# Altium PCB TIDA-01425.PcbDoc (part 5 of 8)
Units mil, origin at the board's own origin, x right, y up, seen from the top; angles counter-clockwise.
Board outline 7000 x 3600 mil, 6 copper layers (Layer 1 - Top Layer, Layer 2 - GND, Layer 3 - Signal / PWR, Layer 4 - Signal / PWR, Layer 5 - PWR, Layer 6 - Bottom Layer), stack 60.4 mil thick; 495 components, 307 nets, 2058 pads, 1870 vias.
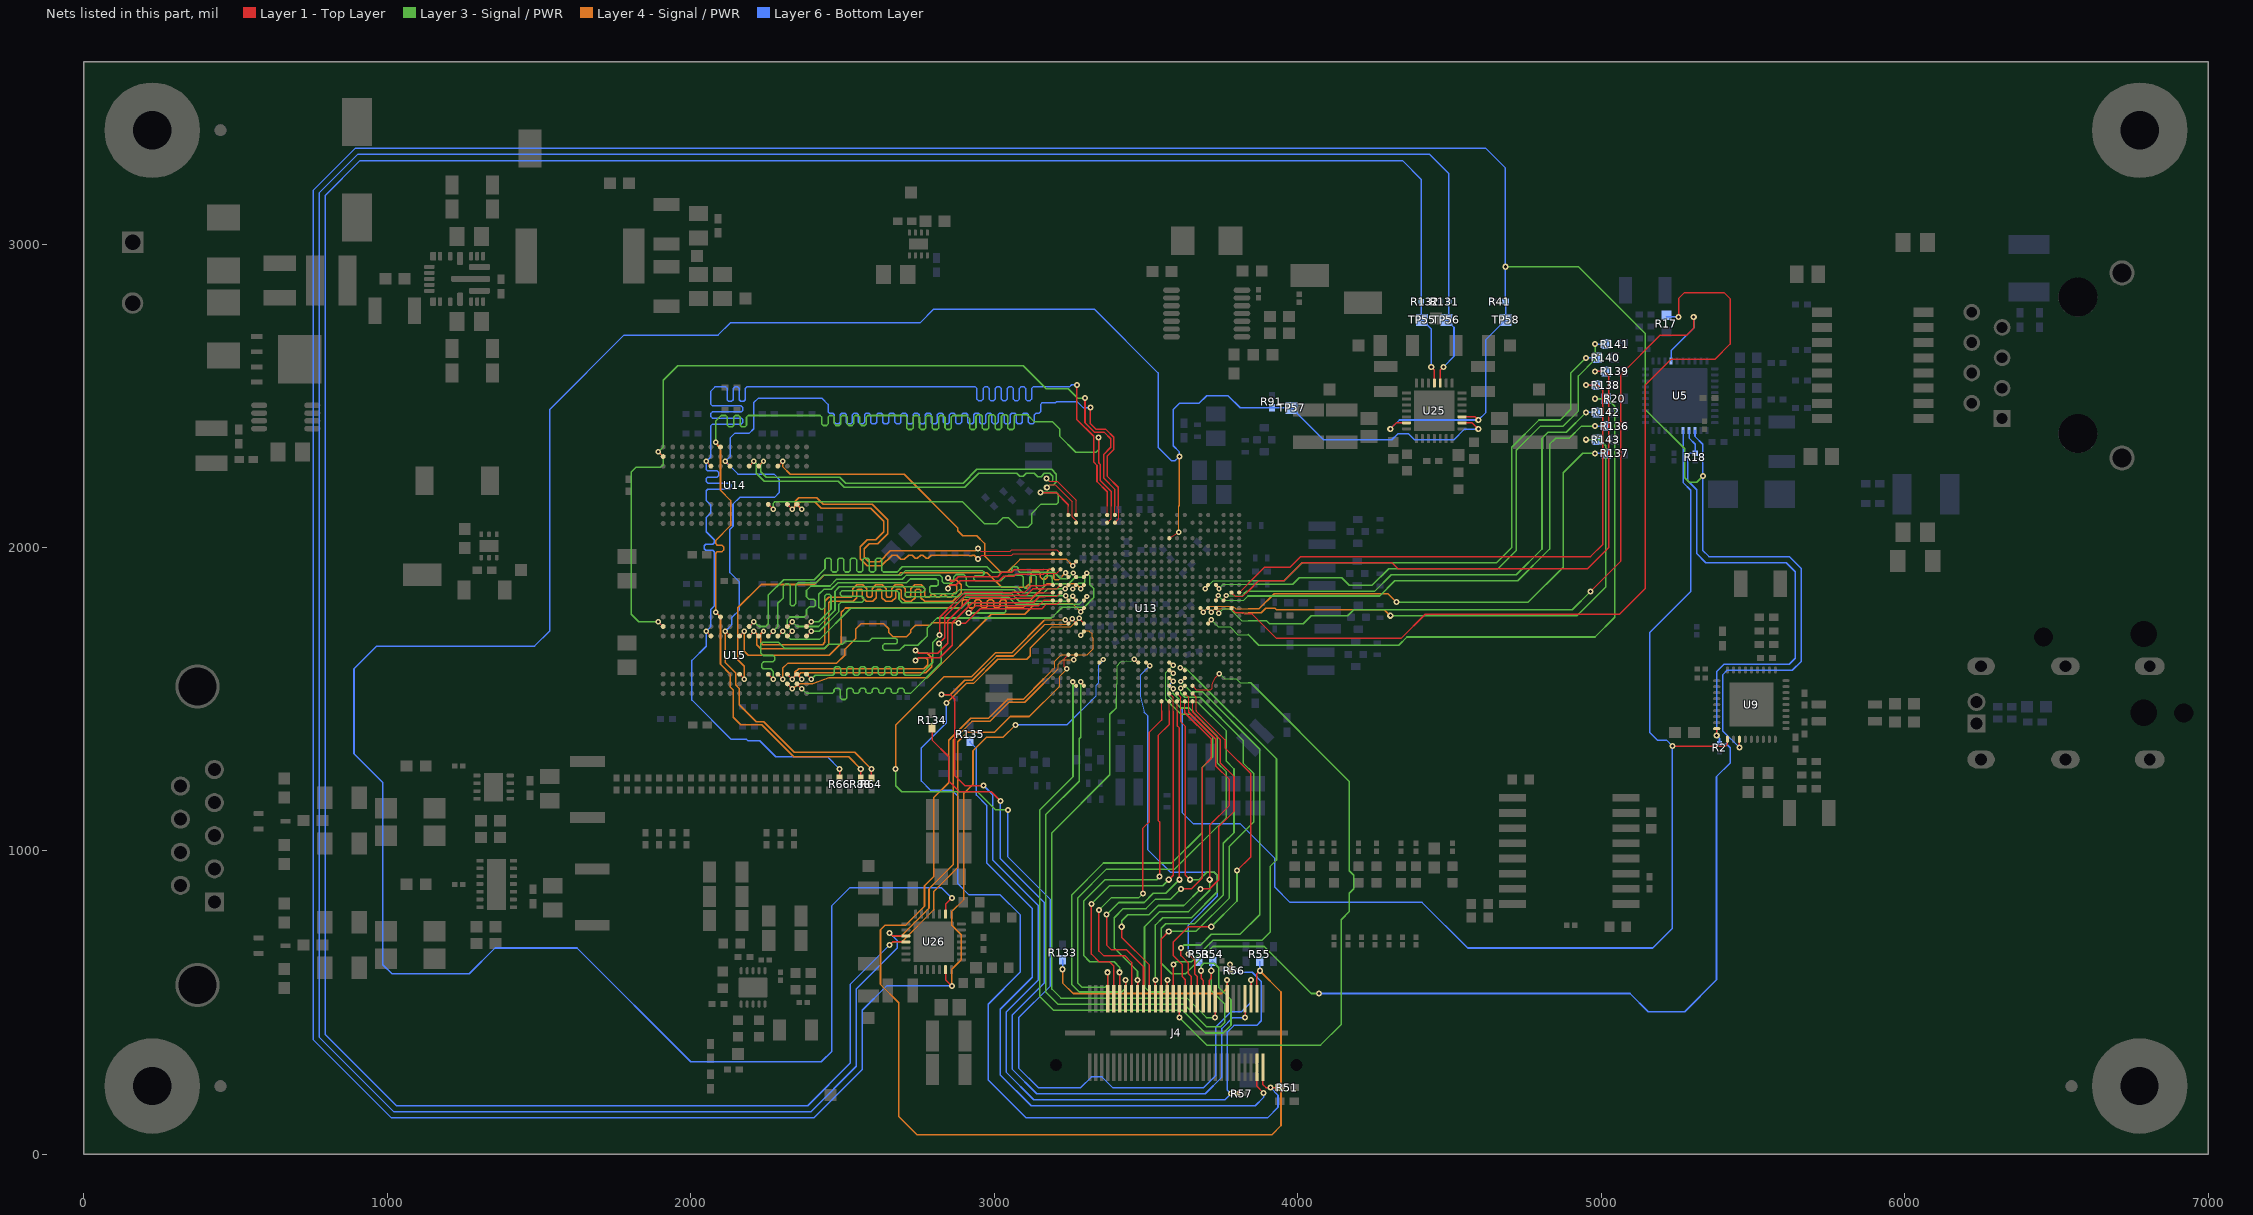
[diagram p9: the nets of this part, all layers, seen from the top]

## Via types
v1: diameter 20, hole 10, Layer 1 - Top Layer to Layer 6 - Bottom Layer, tented both sides, 1119 vias
v2: diameter 20, hole 9.99, Layer 1 - Top Layer to Layer 6 - Bottom Layer, tented both sides, 298 vias
v3: diameter 18, hole 7.99, Layer 1 - Top Layer to Layer 6 - Bottom Layer, tented both sides, 203 vias
v4: diameter 18, hole 8, Layer 1 - Top Layer to Layer 6 - Bottom Layer, tented both sides, 177 vias
v5: diameter 19.68, hole 7.87, Layer 1 - Top Layer to Layer 6 - Bottom Layer, tented both sides, 41 vias
v6: diameter 20, hole 10, Layer 1 - Top Layer to Layer 6 - Bottom Layer, 27 vias
v7: diameter 19.68, hole 7.87, Layer 1 - Top Layer to Layer 6 - Bottom Layer, 5 vias

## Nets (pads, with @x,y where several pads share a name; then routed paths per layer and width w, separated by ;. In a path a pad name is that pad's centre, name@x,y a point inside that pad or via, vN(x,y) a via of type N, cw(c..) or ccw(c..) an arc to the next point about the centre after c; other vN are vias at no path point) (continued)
H_DDR1_D20: U13.T22 U15.E3 | length 1681.3
  Layer 1 - Top Layer w4: U15.E3@2255.24,1707.99 v4(2270.98,1723.73)
  Layer 1 - Top Layer w4.05: v3(3259.1,1863.1) U13.T22@3269.68,1876.77
  Layer 3 - Signal / PWR w5.25: v4(2270.98,1723.73) 2286.84,1739.59 2286.84,1815.84 2304,1833 2304,1871 2313.82,1880.82 2321.18,1880.82 2327,1875 2327,1813.08 2332,1808.08 2339.08,1808.08 2345.2,1814.2 2345.2,1875.2 2353.6,1883.6 2412.5,1883.6 2437.2,1908.3 2692.3,1908.3 2707.8,1923.8 2961.2,1923.8 2966,1919 2966,1911.62 2960.8,1906.42 2936.85,1906.42 2933,1902.57 2933,1895.21 2938.21,1890 3022.51,1890 3036.98,1904.47 3041.55,1904.47 3041.91,1904.83 3043.43,1904.83 3046.4,1907.8 3090.4,1907.8 3095.6,1902.6 3095.6,1871.2 3100.8,1866 3111.2,1866 3116.4,1871.2 3116.4,1902.6 3121.6,1907.8 3134,1907.8 3137.9,1903.9 3137.9,1870.1 3144.82,1863.18 3155.18,1863.18 3163,1871 3163,1899 3171,1907 3185.8,1907 3191,1901.8 3191,1885.2 3196.2,1880 3245,1880 3266.99,1901.99 3293.52,1901.99 3298.72,1896.79 3298.72,1886.72 3294,1882 3278,1882 v3(3259.1,1863.1)
H_DDR1_D21: U13.U22 U15.G2 | length 1680
  Layer 1 - Top Layer w4: U15.G2@2192.24,1739.49 v4(2207.98,1755.22) ; v3(3259.7,1915.8) U13.U22@3269.68,1902.36
  Layer 3 - Signal / PWR w5.25: v4(2207.98,1755.22) 2223.7,1739.5 2246.59,1739.5 2255.3,1748.21 2255.3,1843.37 2305.93,1894 2406.5,1894 2442.2,1929.7 2442.2,1959.8 2447.4,1965 2457.8,1965 2463,1959.8 2463,1924.2 2468.2,1919 2478.6,1919 2483.8,1924.2 2483.8,1959.8 2489,1965 2499.4,1965 2504.6,1959.8 2504.6,1924.2 2509.8,1919 2520.2,1919 2525.4,1924.2 2525.4,1959.8 2530.6,1965 2541,1965 2546.2,1959.8 2546.2,1924.2 2551.4,1919 2561.8,1919 2567,1924.2 2567,1959.8 2572.2,1965 2582.6,1965 2587.8,1959.8 2587.8,1924.2 2593,1919 2603.4,1919 2608.6,1924.2 2608.6,1959.8 2613.8,1965 2624.2,1965 2629.4,1959.8 2629.4,1924.2 2634.6,1919 2680,1919 2697.1,1936.1 2975.9,1936.1 2993.95,1918.05 3052.95,1918.05 3058.15,1923.25 3058.15,1931.8 3063.35,1937 3073.75,1937 3078.95,1931.8 3078.95,1923.25 3084.15,1918.05 3197.95,1918.05 3219,1897 3240.9,1897 v3(3259.7,1915.8)
H_DDR1_D22: U13.U23 U15.H7 | length 1552
  Layer 1 - Top Layer w4: U15.H7@2160.75,1582 v4(2176.49,1566.26) ; v3(3234.8,1916.5) U13.U23@3244.09,1902.36
  Layer 4 - Signal / PWR w5.25: v4(2176.49,1566.26) 2176.49,1608.5 2155,1629.99 2155,1801 2231.9,1877.9 2407.7,1877.9 2438.6,1908.8 2683.8,1908.8 2691,1916 2977,1916 3024.6,1868.4 3103.4,1868.4 3121,1886 3121,1916 3127,1922 3145.8,1922 3151,1916.8 3151,1903 3158.03,1895.97 3169.39,1895.97 3174.59,1901.17 3174.59,1921.8 3180.79,1928 3189.19,1928 3195.39,1921.8 3195.39,1898.2 3200.59,1893 3211.3,1893 v3(3234.8,1916.5)
H_DDR1_D23: U13.T21 U15.H3 | length 1552.8
  Layer 1 - Top Layer w4: U15.H3@2160.75,1707.99 v4(2176.49,1723.73) ; v3(3285.5,1864.1) U13.T21@3295.28,1876.77
  Layer 4 - Signal / PWR w5.25: v4(2176.49,1723.73) 2176.49,1657.51 2189,1645 2456,1645 2495.5,1684.5 2495.5,1786.5 2509.6,1800.6 2888.74,1800.6 2893.94,1805.8 2893.94,1822.8 2899.14,1828 2909.54,1828 2914.74,1822.8 2914.74,1805.8 2919.94,1800.6 2930.34,1800.6 2935.54,1805.8 2935.54,1822.8 2940.74,1828 2951.14,1828 2956.34,1822.8 2956.34,1805.8 2961.54,1800.6 2971.94,1800.6 2977.14,1805.8 2977.14,1822.8 2982.34,1828 2992.74,1828 2997.94,1822.8 2997.94,1805.8 3003.14,1800.6 3013.54,1800.6 3018.74,1805.8 3018.74,1822.8 3023.94,1828 3034.34,1828 3039.54,1822.8 3039.54,1805.8 3044.74,1800.6 3094.6,1800.6 3174,1880 3269.6,1880 v3(3285.5,1864.1)
H_DDR1_D24: U13.T23 U15.C3 | length 1232.6
  Layer 1 - Top Layer w4: U15.C3@2318.23,1707.99 v4(2333.97,1723.73) ; v3(3234.3,1863.7) U13.T23@3244.09,1876.77
  Layer 3 - Signal / PWR w5.25: v4(2333.97,1723.73) 2318.3,1739.4 2318.3,1762.4 2326.8,1770.9 2374.51,1770.9 2381.2,1777.59 2381.2,1795.2 2390,1804 2405,1804 2410,1809 2410,1824.45 2404.75,1829.7 2389.3,1829.7 2381.06,1837.94 2381.06,1858.06 2396.1,1873.1 2458.5,1873.1 2480.4,1895 2697,1895 2711,1909 2820,1909 2829,1900 2829,1887.2 2834.2,1882 2859,1882 2867,1890 2867,1903 2875,1911 2899,1911 2908,1902 2908,1877 2914,1871 3074,1871 3094,1851 3163.99,1851 3176.69,1863.7 v3(3234.3,1863.7)
H_DDR1_D25: U13.T25 U15.A7 | length 1283.8
  Layer 1 - Top Layer w4: U15.A7@2381.22,1582.01 v4(2396.96,1566.26)
  Layer 1 - Top Layer w5: v1(2820,1711) 2820,1770 2901.7,1851.7 3028.37,1851.7 3028.73,1851.34 3059.01,1851.34 3059.37,1851.7 3099.7,1851.7 3122,1874 3161,1874 3163.77,1876.77 U13.T25@3192.91,1876.77
  Layer 3 - Signal / PWR w5.25: v4(2396.96,1566.26) 2409.7,1579 2467.5,1579 2472.7,1584.2 2472.7,1601.8 2477.9,1607 2488.3,1607 2493.5,1601.8 2493.5,1584.2 2498.7,1579 2509.1,1579 2514.3,1584.2 2514.3,1601.8 2519.5,1607 2529.9,1607 2535.1,1601.8 2535.1,1584.2 2540.3,1579 2550.7,1579 2555.9,1584.2 2555.9,1601.8 2561.1,1607 2571.5,1607 2576.7,1601.8 2576.7,1584.2 2581.9,1579 2592.3,1579 2597.5,1584.2 2597.5,1601.8 2602.7,1607 2613.1,1607 2618.3,1601.8 2618.3,1584.2 2623.5,1579 2633.9,1579 2639.1,1584.2 2639.1,1601.8 2644.3,1607 2654.7,1607 2659.9,1601.8 2659.9,1584.2 2665.1,1579 2675.5,1579 2680.7,1584.2 2680.7,1601.8 2685.9,1607 2696.3,1607 2701.5,1601.8 2701.5,1584.2 2706.7,1579 2755,1579 2797.6,1621.6 2797.6,1687.08 2801.37,1690.85 ; 2801.37,1690.89 2820,1709.52 v1(2820,1711)
H_DDR1_D26: U13.T24 U15.B8 | length 1290.2
  Layer 1 - Top Layer w4: U15.B8@2349.72,1550.51 v4(2365.46,1534.77) ; 3163,1864 3205.73,1864 U13.T24@3218.5,1876.77
  Layer 1 - Top Layer w5: v1(2818,1684) 2836.5,1702.5 2836.5,1772.34 2905.86,1841.7 3024.22,1841.7 3024.58,1841.34 3063.16,1841.34 3063.52,1841.7 3105.69,1841.7 3127.99,1864 3163,1864
  Layer 3 - Signal / PWR w5.25: v4(2365.46,1534.77) 2381.34,1518.89 2466.47,1518.89 2471.72,1524.14 2471.72,1530.75 2476.97,1536 2487.47,1536 2492.72,1530.75 2492.72,1504.14 2497.97,1498.89 2508.47,1498.89 2513.72,1504.14 2513.72,1530.75 2518.97,1536 2529.47,1536 2534.72,1530.75 2534.72,1524.14 2539.97,1518.89 2550.47,1518.89 2555.72,1524.14 2555.72,1530.75 2560.97,1536 2571.47,1536 2576.72,1530.75 2576.72,1524.14 2581.97,1518.89 2592.47,1518.89 2597.72,1524.14 2597.72,1530.75 2602.97,1536 2613.47,1536 2618.72,1530.75 2618.72,1524.14 2623.97,1518.89 2634.47,1518.89 2639.72,1524.14 2639.72,1530.75 2644.97,1536 2655.47,1536 2660.72,1530.75 2660.72,1524.14 2665.97,1518.89 2676.47,1518.89 2681.72,1524.14 2681.72,1530.75 2686.97,1536 2697.47,1536 2702.72,1530.75 2702.72,1524.14 2707.97,1518.89 2723.89,1518.89 2825,1620 2825,1677 v1(2818,1684)
H_DDR1_D27: U13.P21 U15.A3 | length 1235.1
  Layer 1 - Top Layer w4: U15.A3@2381.22,1707.99 v4(2396.96,1723.73)
  Layer 1 - Top Layer w4.05: U13.P21@3295.28,1825.59 v3(3305.5,1838.3)
  Layer 3 - Signal / PWR w5.25: v4(2396.96,1723.73) 2423.16,1723.73 2488,1788.57 2488,1812 2496,1820 2564.8,1820 2570,1825.2 2570,1832.56 2563.32,1839.24 2498.2,1839.24 2493,1844.44 2493,1851.8 2498.2,1857 2679,1857 2686,1850 2686,1829 2697,1818 2882,1818 2900,1836 3048,1836 3071.64,1812.36 3279.56,1812.36 v3(3305.5,1838.3)
H_DDR1_D28: U13.N21 U15.C8 | length 1110.4
  Layer 1 - Top Layer w4: U15.C8@2318.23,1550.51 v4(2333.97,1534.77) ; v3(3285.6,1787.5) U13.N21@3295.28,1800
  Layer 4 - Signal / PWR w5.25: v4(2333.97,1534.77) 2360.46,1550.5 2401.43,1550.5 2454.6,1570 2780,1570 2990,1780 3100,1780 3135.1,1815.1 3258,1815.1 v3(3285.6,1787.5)
H_DDR1_D29: U13.P22 U15.C2 | length 1235.8
  Layer 1 - Top Layer w4: U15.C2@2318.23,1739.49 v4(2333.97,1755.22)
  Layer 1 - Top Layer w4.05: v3(3258.8,1839.9) U13.P22@3269.68,1825.59
  Layer 3 - Signal / PWR w5.25: v4(2333.97,1755.22) 2349.79,1739.4 2421.1,1739.4 2475,1793.3 2475,1856 2489.5,1870.5 2765.5,1870.5 2771,1865 2771,1859 2765,1853 2711,1853 2706,1848 2706,1842 2711,1837 2881,1837 2892,1848 3057,1848 3082.39,1822.61 3241.51,1822.61 v3(3258.8,1839.9)
H_DDR1_D30: U13.P23 U15.A2 | length 1236.7
  Layer 1 - Top Layer w4: U15.A2@2381.22,1739.49 v4(2396.96,1755.22) ; v3(3235.9,1840.6) U13.P23@3244.09,1825.59
  Layer 3 - Signal / PWR w5.25: v4(2396.96,1755.22) 2421.22,1755.22 2462,1796 2462,1840.8 2456.8,1846 2447.2,1846 2442,1840.8 2442,1803.6 2435.4,1797 2428.04,1797 2422,1803.04 2422,1845.57 2438.56,1862.13 2462.92,1862.13 2483.79,1883 2710,1883 2723,1896 2809,1896 2815,1890 2815,1877 2811,1873 2791,1873 2787,1869 2787,1853 2792.75,1847.25 2871.25,1847.25 2884,1860 3066,1860 3085.4,1840.6 v3(3235.9,1840.6)
H_DDR1_D31: U13.P24 U15.D7 | length 1143.4
  Layer 1 - Top Layer w4: U15.D7@2286.73,1582.01 v4(2302.47,1566.26) ; 3163,1804.41 3171.39,1812.8 3205.71,1812.8 U13.P24@3218.5,1825.59
  Layer 1 - Top Layer w5: v1(2882.66,1750.74) 2905.99,1750.74 2922.75,1767.5 2953.56,1798.3 3006.23,1798.3 3006.59,1797.94 3081.15,1797.94 3081.51,1798.3 3156.89,1798.3 3163,1804.41
  Layer 4 - Signal / PWR w5.25: v4(2302.47,1566.26) 2302.47,1601.47 2320,1619 2481,1619 2507,1645 2507,1664 2544,1701 2544,1732 2560,1748 2636.2,1748 2652,1732.2 2652,1720 2666,1706 2711,1706 2725,1720 2725,1728 2740,1743 2786.2,1743 2794.98,1751.78 2881.62,1751.78 v1(2882.66,1750.74)
H_DDR1_DQM0: U13.AE23 U14.E7 | length 1317.5
  Layer 1 - Top Layer w4: U14.E7@2255.24,2142.01 v4(2270.98,2126.26) ; U13.AE23@3244.09,2107.09 3244.09,2136
  Layer 1 - Top Layer w5: v1(3153,2181) 3204,2181 3244.09,2140.91 3244.09,2136
  Layer 3 - Signal / PWR w5.25: v4(2270.98,2126.26) 2270.98,2144.98 2277,2151 2895,2151 2968,2078 3009,2078 3029,2098 3047,2098 3079,2066 3110,2066 3124,2080 3124,2113 3154,2143 3205.8,2143 3211,2148.2 3211,2175.05 3205.05,2181 v1(3153,2181)
H_DDR1_DQM1: U13.W22 U14.D3 | length 1211.9
  Layer 1 - Top Layer w4: U14.D3@2286.73,2267.99 v4(2302.47,2283.73) ; v3(3258.7,1940) U13.W22@3269.68,1953.54
  Layer 4 - Signal / PWR w5.25: v4(2302.47,2283.73) 2302.47,2266.53 2328,2241 2703,2241 2880,2064 2880,2055 2896.1,2038.9 2942.1,2038.9 2968,2013 2968,1973 3022.5,1918.5 3042.9,1918.5 3084.9,1960.5 3238.2,1960.5 v3(3258.7,1940)
H_DDR1_DQM2: U13.U21 U15.E7 | length 1679.2
  Layer 1 - Top Layer w4: U15.E7@2255.24,1582.01 v4(2270.98,1566.26)
  Layer 1 - Top Layer w4.05: U13.U21@3295.28,1902.36 v3(3304.3,1915.7)
  Layer 3 - Signal / PWR w5.25: v4(2270.98,1566.26) 2270.98,1592 2262.98,1600 2238.47,1600 2233.22,1605.25 2233.22,1616.21 2240.63,1623.62 2270.61,1623.62 2276.28,1629.29 2276.28,1638.72 2271,1644 2238,1644 2231,1651 2231,1683 2235,1687 2290,1687 2309,1668 2441,1668 2454,1681 2500,1681 2510,1691 2587,1691 2597,1701 2674.75,1701 2680,1695.75 2680,1686 2676,1682 2638.25,1682 2633,1676.75 2633,1666.25 2638.25,1661 2688,1661 2704.63,1677.63 2748.13,1677.63 2779.6,1709.1 2779.6,1735.36 2811.61,1767.37 3188.37,1767.37 3224.12,1803.12 3296.12,1803.12 3328,1835 3328,1865.01 3314,1879.01 3314,1906 v3(3304.3,1915.7)
H_DDR1_DQM3: U13.P25 U15.D3 | length 1263.6
  Layer 1 - Top Layer w4: U15.D3@2286.73,1707.99 v4(2302.47,1723.73)
  Layer 1 - Top Layer w5: v1(2915.92,1784) 2940.22,1808.3 3010.38,1808.3 3010.74,1807.94 3077,1807.94 3077.36,1808.3 3146.29,1808.3 3163.58,1825.59 U13.P25@3192.91,1825.59
  Layer 3 - Signal / PWR w5.25: v4(2302.47,1723.73) 2329.2,1697 2424,1697 2527,1800 2892,1800 2910,1818 3032.75,1818 3038,1812.75 3038,1789 3033,1784 v1(2915.92,1784)
H_DDR1_DQS0_N: U13.AE22 U14.G3 | length 1316.8
  Layer 1 - Top Layer w4: v1(3172,2227) 3181,2218 3208,2218 3269.81,2156.19 3269.81,2117.96 3269.86,2117.91 3269.86,2107.26 U13.AE22@3269.68,2107.09
  Layer 1 - Top Layer w4.05: U14.G3@2192.24,2267.99 v4(2207.98,2283.73)
  Layer 3 - Signal / PWR w4: v1(3172,2227) 3181,2218 3189,2218 3193,2222
  Layer 3 - Signal / PWR w4.5: v4(2207.98,2283.73) 2216,2275.71 2216,2243.99 2241.99,2218 2485.2,2218 2505.2,2198 2902.8,2198 2948.8,2244 3074,2244 3084,2234 3095,2234 3105,2244 3132,2244 3143,2233 3154,2233 3165,2244 3183.2,2244 3193,2234.2 3193,2222
H_DDR1_DQS0_P: U13.AD22 U14.F3 | length 1328
  Layer 1 - Top Layer w4: v1(3173,2198) 3182,2207 3200.61,2207 3256.81,2150.8 3256.81,2117.92
  Layer 1 - Top Layer w4.05: U14.F3@2223.74,2267.99 v4(2239.48,2283.73) ; 3256.81,2117.92 3256.81,2101.53 3269.69,2088.65 U13.AD22@3269.68,2081.5
  Layer 3 - Signal / PWR w4: v1(3173,2198) 3173,2199 3181,2207 3196,2207
  Layer 3 - Signal / PWR w4.5: v4(2239.48,2283.73) 2230,2274.25 2230,2249.79 2247.79,2232 2491,2232 2511,2212 2897,2212 2943,2258 3189,2258 3205,2242 3205,2216 3196,2207
H_DDR1_DQS1_N: U13.Y25 U14.B7 | length 1229.4
  Layer 1 - Top Layer w4: v1(2947,1961.66) 2959.45,1974.11 3005.89,1974.11 3006,1974 3057.39,1974 3062.41,1979.02 3074.96,1979.02 3075.07,1979.13 3182.16,1979.13 3182.26,1979.03 3192.81,1979.03 U13.Y25@3192.91,1979.13
  Layer 1 - Top Layer w4.05: U14.B7@2349.72,2142.01 v4(2365.46,2126.26)
  Layer 4 - Signal / PWR w4.5: v4(2365.46,2126.26) 2356,2135.72 2356,2145 2361,2150 2409.18,2150 2430.58,2128.6 2592.6,2128.6 2635.6,2085.6 2635.6,2051.6 2610,2026 2582,2026 2558,2002 2558,1962.2 2581.2,1939 2627.8,1939 2663.8,1975 2678,1975 2692,1961 2704,1961 2718,1975 2729,1975 2739.81,1964.19 2746.19,1964.19 2757,1975 2765,1975 2775.81,1964.19 2782.19,1964.19 2793,1975 2916,1975 2918.81,1972.19 2925.19,1972.19 2928,1975 2933.66,1975 v1(2947,1961.66)
H_DDR1_DQS1_P: U13.Y24 U14.C7 | length 1247.3
  Layer 1 - Top Layer w4: v1(2947,1996.34) 2956.23,1987.11 2986.7,1987.11 2986.81,1987 3052,1987 3057.02,1992.02 3069.57,1992.02 3069.68,1992.13 3187.55,1992.13 3187.65,1992.03 3205.6,1992.03 U13.Y24@3218.5,1979.13
  Layer 1 - Top Layer w4.05: U14.C7@2318.23,2142.01 v4(2333.97,2126.26)
  Layer 4 - Signal / PWR w4.5: v4(2333.97,2126.26) 2342,2134.29 2342,2150.8 2355.2,2164 2414.98,2164 2436.38,2142.6 2598.4,2142.6 2649.6,2091.4 2649.6,2045.8 2615.8,2012 2587.8,2012 2572,1996.2 2572,1968 2587,1953 2622,1953 2658,1989 2939.66,1989 v1(2947,1996.34)
H_DDR1_DQS2_N: U13.V25 U15.G3 | length 1600
  Layer 1 - Top Layer w4: 3163,1927.5 3163.55,1928.05 3192.81,1928.05 U13.V25@3192.91,1927.95
  Layer 1 - Top Layer w4.05: U15.G3@2192.24,1707.99 v4(2207.98,1723.73)
  Layer 1 - Top Layer w4.4: v1(2847,1899.34) 2857.34,1889 2867,1889 2882,1904 3011,1904 3025.4,1918.4 3058.4,1918.4 3066.5,1926.5 3162,1926.5 3163,1927.5
  Layer 4 - Signal / PWR w4.5: v4(2207.98,1723.73) 2216.73,1714.98 2216.73,1679.91 2230.64,1666 2439.8,1666 2455,1681.2 2455,1817.5 2459.5,1822 2534.7,1822 2547.4,1834.7 2547.4,1858.5 2551.9,1863 2560.9,1863 2565.4,1858.5 2565.4,1834.7 2578.1,1822 2598.7,1822 2611.4,1834.7 2611.4,1858.5 2615.9,1863 2624.9,1863 2629.4,1858.5 2629.4,1834.7 2642.1,1822 2662.7,1822 2675.4,1834.7 2675.4,1858.5 2679.9,1863 2688.9,1863 2693.4,1858.5 2693.4,1834.7 2706.1,1822 2726.7,1822 2739.4,1834.7 2739.4,1858.5 2743.9,1863 2752.9,1863 2757.4,1858.5 2757.4,1834.7 2770.1,1822 2863,1822 2891,1850 2891,1877.3 2876.4,1891.9 2854.44,1891.9 v1(2847,1899.34)
H_DDR1_DQS2_P: U13.V24 U15.F3 | length 1586.2
  Layer 1 - Top Layer w4: 3163,1913.5 3163.85,1914.35 3186.95,1914.35 3187.65,1915.05 3205.6,1915.05 3205.76,1915.21
  Layer 1 - Top Layer w4.05: U15.F3@2223.74,1707.99 v4(2239.48,1723.73) ; 3205.76,1915.21 U13.V24@3218.5,1927.95
  Layer 1 - Top Layer w4.4: v1(2847,1864.66) 2857.34,1875 2872.8,1875 2887.8,1890 3016.8,1890 3031.2,1904.4 3064.2,1904.4 3072.3,1912.5 3162,1912.5 3163,1913.5
  Layer 4 - Signal / PWR w4.5: v4(2239.48,1723.73) 2230.73,1714.98 2230.73,1685.71 2236.44,1680 2434,1680 2441,1687 2441,1823.3 2453.7,1836 2528.9,1836 2533.4,1840.5 2533.4,1864.3 2546.1,1877 2566.7,1877 2579.4,1864.3 2579.4,1840.5 2583.9,1836 2592.9,1836 2597.4,1840.5 2597.4,1864.3 2610.1,1877 2630.7,1877 2643.4,1864.3 2643.4,1840.5 2647.9,1836 2656.9,1836 2661.4,1840.5 2661.4,1864.3 2674.1,1877 2694.7,1877 2707.4,1864.3 2707.4,1840.5 2711.9,1836 2720.9,1836 2725.4,1840.5 2725.4,1864.3 2738.1,1877 2758.7,1877 2771.4,1864.3 2771.4,1840.5 2775.9,1836 2785,1836 2794.31,1845.31 2800.69,1845.31 2810,1836 2819,1836 2829.31,1846.31 2835.69,1846.31 2846,1836 2857.2,1836 2863.6,1842.4 2863.6,1846.9 2868.1,1851.4 2872.6,1851.4 2877,1855.8 2877,1871.5 2870.6,1877.9 2854.9,1877.9 2847,1870 v1(2847,1864.66)
H_DDR1_DQS3_N: U13.R25 U15.B7 | length 1163.9
  Layer 1 - Top Layer w4: 3163,1851 3192.73,1851 U13.R25@3192.91,1851.18
  Layer 1 - Top Layer w4.05: U15.B7@2349.72,1582.01 v4(2365.46,1566.26)
  Layer 1 - Top Layer w4.4: v1(2741,1661) 2750.85,1651.15 2814.15,1651.15 2847,1684 2847,1757.8 2921.2,1832 3020.2,1832 3020.56,1831.64 3067.18,1831.64 3067.54,1832 3123,1832 3142,1851 3163,1851
  Layer 4 - Signal / PWR w4.5: v4(2365.46,1566.26) 2357,1574.72 2357,1582.5 2361.5,1587 2774,1587 2794,1607 2794,1636 2778.85,1651.15 2750.85,1651.15 v1(2741,1661)
H_DDR1_DQS3_P: U13.R24 U15.C7 | length 1172.3
  Layer 1 - Top Layer w4: 3163,1837 3168.52,1837 3170,1838.48 3205.8,1838.48 U13.R24@3218.5,1851.18
  Layer 1 - Top Layer w4.05: U15.C7@2318.23,1582.01 v4(2333.97,1566.26)
  Layer 1 - Top Layer w4.4: v1(2741,1627.31) 2750.84,1637.15 2819.95,1637.15 2861,1678.2 2861,1752 2927,1818 3014.4,1818 3014.76,1817.64 3072.98,1817.64 3073.34,1818 3128.8,1818 3147.8,1837 3163,1837
  Layer 4 - Signal / PWR w4.5: v4(2333.97,1566.26) 2343,1575.29 2343,1588.3 2355.7,1601 2768.2,1601 2780,1612.8 2780,1630.2 2773.05,1637.15 2750.84,1637.15 v1(2741,1627.31)
H_DDR1_ODT0: R88.1 U13.AD18 U14.K1 U15.K1 | length 4323.8
  Layer 1 - Top Layer w4: v4(2082.02,1786.72) U15.K1@2097.76,1770.98 ; v4(2082.02,2346.72) U14.K1@2097.76,2330.98 ; U13.AD18@3372.05,2081.5 3384.74,2094.19 3384.74,2136
  Layer 1 - Top Layer w5: R88.1@2560,1239.68 v1(2560,1270) ; v1(3344,2362) 3344,2279 3348.5,2274.5 3348.5,2221.42 3384.74,2185.18 3384.74,2136
  Layer 3 - Signal / PWR w5.25: v4(2082.02,2346.72) 2082.02,2416.52 2100.4,2434.9 2115.29,2434.9 2120.54,2429.65 2120.54,2402.35 2125.79,2397.1 2136.29,2397.1 2141.54,2402.35 2141.54,2429.65 2146.79,2434.9 2157.29,2434.9 2162.54,2429.65 2162.54,2402.35 2167.79,2397.1 2178.29,2397.1 2183.54,2402.35 2183.54,2429.65 2188.79,2434.9 2425.98,2434.9 2431.23,2429.65 2431.23,2407.05 2436.48,2401.8 2446.98,2401.8 2452.23,2407.05 2452.23,2429.65 2457.48,2434.9 2467.98,2434.9 2473.23,2429.65 2473.23,2407.05 2478.48,2401.8 2488.98,2401.8 2494.23,2407.05 2494.23,2429.65 2499.48,2434.9 2509.98,2434.9 2515.23,2429.65 2515.23,2407.05 2520.48,2401.8 2530.98,2401.8 2536.23,2407.05 2536.23,2429.65 2541.48,2434.9 2551.98,2434.9 2557.23,2429.65 2557.23,2407.05 2562.48,2401.8 2572.98,2401.8 2578.23,2407.05 2578.23,2429.65 2583.48,2434.9 2706.34,2434.9 2711.59,2429.65 2711.59,2393.95 2716.84,2388.7 2727.34,2388.7 2732.59,2393.95 2732.59,2429.65 2737.84,2434.9 2748.34,2434.9 2753.59,2429.65 2753.59,2393.95 2758.84,2388.7 2769.34,2388.7 2774.59,2393.95 2774.59,2429.65 2779.84,2434.9 2790.34,2434.9 2795.59,2429.65 2795.59,2393.95 2800.84,2388.7 2811.34,2388.7 2816.59,2393.95 2816.59,2429.65 2821.84,2434.9 2832.34,2434.9 2837.59,2429.65 2837.59,2393.95 2842.84,2388.7 2853.34,2388.7 2858.59,2393.95 2858.59,2429.65 2863.84,2434.9 2908.41,2434.9 2918.71,2424.6 2918.71,2393.95 2923.96,2388.7 2934.46,2388.7 2939.71,2393.95 2939.71,2432.45 2944.96,2437.7 2955.46,2437.7 2960.71,2432.45 2960.71,2393.95 2965.96,2388.7 2976.46,2388.7 2981.71,2393.95 2981.71,2432.45 2986.96,2437.7 2997.46,2437.7 3002.71,2432.45 3002.71,2393.95 3007.96,2388.7 3018.46,2388.7 3023.71,2393.95 3023.71,2432.45 3028.96,2437.7 3039.46,2437.7 3044.71,2432.45 3044.71,2393.95 3049.96,2388.7 3060.46,2388.7 3065.71,2393.95 3065.71,2432.45 3070.96,2437.7 3108.6,2437.7 3132.7,2413.6 3192.91,2413.6 3215.1,2391.41 3215.1,2367.1 3268.2,2314 3335,2314 3344,2323 v1(3344,2362)
  Layer 4 - Signal / PWR w5.25: v4(2082.02,2346.72) 2097.88,2320.3 2097.88,2188.11 2131,2154.99 2131,2071.99 2082.03,2023.02 2082.02,2022.97 2082.02,2012.72 2087.27,2007.47 2102.75,2007.47 2108,2002.22 2108,1991.72 2102.75,1986.47 2087.27,1986.47 2082.02,1981.22 v4(2082.02,1786.72) 2097.7,1771.04 2097.7,1614.8 2130,1582.5 2130,1540 2140,1530 2140,1440.1 2164.6,1415.5 2233.6,1415.5 2339.1,1310 2520,1310 v1(2560,1270)
H_DDR1_RASN: R64.2 U13.AD17 U14.J3 U15.J3 | length 4603.4
  Layer 1 - Top Layer w4: v4(2113.51,1723.73) U15.J3@2129.25,1707.99 ; v4(2113.51,2283.73) U14.J3@2129.25,2267.99 ; U13.AD17@3397.64,2081.5 3410.33,2094.19 3410.33,2124.67 3408.49,2126.51 3408.49,2136
  Layer 1 - Top Layer w5: R64.2@2595,1239.69 v1(2595,1270) ; v1(3317,2461) 3317,2408 3336,2389 3368,2389 3394,2363 3394,2323 3373,2302 3373,2234 3408.49,2198.51 3408.49,2136
  Layer 4 - Signal / PWR w5.25: v4(2113.51,1723.73) 2113.51,1620.49 2147.75,1586.25 2147.75,1547.25 2160,1535 2160,1482 2216,1426 2240,1426 2341,1325 2540,1325 v1(2595,1270)
  Layer 6 - Bottom Layer w5: v4(2113.51,1723.73) 2134.4,1744.62 2134.4,1768.41 2160,1794.01 2160,1886 2129,1917 2129,2060 2139,2070 2139,2142.99 2161.01,2165 2276.01,2165 2291,2179.99 2291,2224.99 2273.99,2242 2155.24,2242 v4(2113.51,2283.73) 2129.3,2299.52 2129.3,2360.7 2144.2,2375.6 2191.8,2375.6 2207.7,2391.5 2207.7,2477.3 2222.7,2492.3 2431.6,2492.3 2452.4,2471.5 2452.4,2447.1 2457.4,2442.1 2467.4,2442.1 2472.4,2437.1 2472.4,2412.8 2477.4,2407.8 2487.4,2407.8 2492.4,2412.8 2492.4,2437.1 2497.4,2442.1 2507.4,2442.1 2512.4,2437.1 2512.4,2412.8 2517.4,2407.8 2527.4,2407.8 2532.4,2412.8 2532.4,2437.1 2537.4,2442.1 2547.4,2442.1 2552.4,2437.1 2552.4,2412.8 2557.4,2407.8 2567.4,2407.8 2572.4,2412.8 2572.4,2437.1 2577.4,2442.1 2587.4,2442.1 2592.4,2437.1 2592.4,2412.8 2597.4,2407.8 2607.4,2407.8 2612.4,2412.8 2612.4,2437.1 2617.4,2442.1 2627.4,2442.1 2632.4,2437.1 2632.4,2412.8 2637.4,2407.8 2647.4,2407.8 2652.4,2412.8 2652.4,2437.1 2657.4,2442.1 2667.4,2442.1 2672.4,2437.1 2672.4,2412.8 2677.4,2407.8 2687.4,2407.8 2692.4,2412.8 2692.4,2437.1 2697.4,2442.1 2707.4,2442.1 2712.4,2437.1 2712.4,2412.8 2717.4,2407.8 2727.4,2407.8 2732.4,2412.8 2732.4,2437.1 2737.4,2442.1 2747.4,2442.1 2752.4,2437.1 2752.4,2412.8 2757.4,2407.8 2767.4,2407.8 2772.4,2412.8 2772.4,2437.1 2777.4,2442.1 2787.4,2442.1 2792.4,2437.1 2792.4,2412.8 2797.4,2407.8 2807.4,2407.8 2812.4,2412.8 2812.4,2437.1 2817.4,2442.1 2827.4,2442.1 2832.4,2437.1 2832.4,2412.8 2837.4,2407.8 2847.4,2407.8 2852.4,2412.8 2852.4,2437.1 2857.4,2442.1 2867.4,2442.1 2872.4,2437.1 2872.4,2412.8 2877.4,2407.8 2887.4,2407.8 2892.4,2412.8 2892.4,2437.1 2897.4,2442.1 2907.4,2442.1 2912.4,2437.1 2912.4,2412.8 2917.4,2407.8 2927.4,2407.8 2932.4,2412.8 2932.4,2437.1 2937.4,2442.1 2947.4,2442.1 2952.4,2437.1 2952.4,2412.8 2957.4,2407.8 2967.4,2407.8 2972.4,2412.8 2972.4,2437.1 2977.4,2442.1 2987.4,2442.1 2992.4,2437.1 2992.4,2412.8 2997.4,2407.8 3007.4,2407.8 3012.4,2412.8 3012.4,2437.1 3017.4,2442.1 3027.4,2442.1 3032.4,2437.1 3032.4,2412.8 3037.4,2407.8 3047.4,2407.8 3052.4,2412.8 3052.4,2437.1 3057.4,2442.1 3067.4,2442.1 3072.4,2437.1 3072.4,2412.8 3077.4,2407.8 3087.4,2407.8 3092.4,2412.8 3092.4,2437.1 3097.4,2442.1 3107.4,2442.1 3112.4,2437.1 3112.4,2412.8 3117.4,2407.8 3127.4,2407.8 3132.4,2412.8 3132.4,2437.1 3137.4,2442.1 3147.4,2442.1 3152.4,2447.1 3152.4,2471.5 3157.4,2476.5 3201,2476.5 3204,2479.5 3274,2479.5 3292.5,2461 v1(3317,2461)
H_DDR1_RST: U13.AE17 U14.T2 U15.T2 | length 2936.7
  Layer 1 - Top Layer w4: v4(1893.04,1755.22) U15.T2@1908.78,1739.49 ; v4(1893.04,2315.22) U14.T2@1908.78,2299.49 ; U13.AE17@3397.64,2107.09 3397.64,2136
  Layer 1 - Top Layer w5: v1(3299,2492) 3299,2410.99 3330.99,2379 3362.99,2379 3384,2357.99 3384,2330 3360.5,2306.5 3360.5,2228.49 3397.64,2191.35 3397.64,2136
  Layer 3 - Signal / PWR w5.25: v4(1893.04,1755.22) 1828.78,1755.22 1804,1780 1804,2249 1819,2264 1900.01,2264 1908.9,2272.89 1908.9,2299.36 v4(1893.04,2315.22) 1908.9,2331.08 1908.9,2550.81 1956.69,2598.6 3095.9,2598.6 3171.4,2523.1 3244.2,2523.1 3275.3,2492 v1(3299,2492)
H_DDR1_WEN: R66.1 U13.AE18 U14.L3 U15.L3 | length 4647.5
  Layer 1 - Top Layer w4: v4(2050.52,1723.73) U15.L3@2066.26,1707.99 ; v4(2050.52,2283.73) U14.L3@2066.26,2267.99 ; U13.AE18@3372.05,2107.09 3372.05,2136
  Layer 1 - Top Layer w5: R66.1@2490,1239.68 v1(2490,1270) ; v1(3272,2536) 3272,2422 3327.5,2366.5 3327.5,2281.35 3338.5,2270.35 3338.5,2217.27 3372.05,2183.72 3372.05,2136
  Layer 6 - Bottom Layer w5: v1(2490,1270) 2450,1310 2280,1310 2227,1363 2188,1363 2183.78,1367.22 2133.14,1367.22 2003.52,1496.84 2003.52,1627.52 2050.52,1674.52 v4(2050.52,1723.73) 2066.02,1739.23 2066.02,1796.01 2077,1806.99 2077,1985.5 2072,1990.5 2049,1990.5 2044,1995.5 2044,2005.5 2049,2010.5 2072,2010.5 2077,2015.5 2077,2025.5 2050.52,2051.98 2050.52,2098.53 2066.02,2114.03 2066.02,2138.97 2050.52,2154.47 2050.52,2187.06 2055.52,2192.06 2126.75,2192.06 2131.75,2197.06 2131.75,2207.06 2126.75,2212.06 2055.52,2212.06 2050.52,2217.06 2050.52,2227.06 2055.52,2232.06 2087,2232.06 2092,2237.06 2092,2247.06 2087,2252.06 2055.52,2252.06 2050.52,2257.06 v4(2050.52,2283.73) 2066.02,2299.23 2066.02,2401.5 2071.02,2406.5 2166.3,2406.5 2171.3,2411.5 2171.3,2421.5 2166.3,2426.5 2071.02,2426.5 2066.02,2431.5 2066.02,2441.5 2071.02,2446.5 2166.3,2446.5 2171.3,2451.5 2171.3,2461.5 2166.3,2466.5 2071.02,2466.5 2066.02,2471.5 2066.02,2515.32 2079.5,2528.8 2114.45,2528.8 2119.45,2523.8 2119.45,2486.5 2124.45,2481.5 2134.45,2481.5 2139.45,2486.5 2139.45,2523.8 2144.45,2528.8 2154.45,2528.8 2159.45,2523.8 2159.45,2486.5 2164.45,2481.5 2174.45,2481.5 2179.45,2486.5 2179.45,2523.8 2184.45,2528.8 2937.97,2528.8 2942.97,2523.8 2942.97,2489.1 2947.97,2484.1 2957.97,2484.1 2962.97,2489.1 2962.97,2523.8 2967.97,2528.8 2977.97,2528.8 2982.97,2523.8 2982.97,2489.1 2987.97,2484.1 2997.97,2484.1 3002.97,2489.1 3002.97,2523.8 3007.97,2528.8 3017.97,2528.8 3022.97,2523.8 3022.97,2489.1 3027.97,2484.1 3037.97,2484.1 3042.97,2489.1 3042.97,2523.8 3047.97,2528.8 3057.97,2528.8 3062.97,2523.8 3062.97,2489.1 3067.97,2484.1 3077.97,2484.1 3082.97,2489.1 3082.97,2523.8 3087.97,2528.8 3097.97,2528.8 3102.97,2523.8 3102.97,2489.1 3107.97,2484.1 3117.97,2484.1 3122.97,2489.1 3122.97,2523.8 3127.97,2528.8 3247.8,2528.8 3255,2536 v1(3272,2536)
H_EMU0: J4.19 R54.1 U13.C21 | length 2047.4
  Layer 1 - Top Layer w4: v3(3284.9,1556.8) 3295.2,1546.5 U13.C21@3295.2,1544
  Layer 1 - Top Layer w5.25: J4.19@3708.27,512.8 3708.27,573.27 3715,580 v1(3715,605)
  Layer 3 - Signal / PWR w5.25: v3(3284.9,1556.8) 3284.9,1374.4 3279.75,1369.25 3279.75,1229.75 3170,1120 3170,535 3210,495 3625,495 3700,420 3745,420 3760,435 3760,495 3715,540 v1(3715,605)
  Layer 6 - Bottom Layer w5.25: v1(3715,605) 3715,631.38 R54.1@3720,636.38
H_EMU1: J4.21 R53.1 U13.C22 | length 2208.4
  Layer 1 - Top Layer w4: v3(3259.3,1556.7) U13.C22@3269.59,1544.02
  Layer 1 - Top Layer w5.25: v1(3681.86,605) 3681.86,580 3688.59,573.27 J4.21@3688.59,512.8
  Layer 3 - Signal / PWR w5.25: v3(3259.3,1556.7) 3259.3,1244.3 3150,1135 3150,520.52 3195.52,475 3620,475 3695,400 3755,400 3780,425 3780,510 3740,550 3740,615 3725,630 3690,630 3681.86,621.86 v1(3681.86,605)
  Layer 6 - Bottom Layer w5.25: R53.1@3675,636.38 3681.86,629.52 v1(3681.86,605)
H_EMU2: J4.13 R133.2 | length 730.3
  Layer 1 - Top Layer w5: J4.13@3767.33,512.8 v1(3767.33,575)
  Layer 4 - Signal / PWR w5.25: v1(3225,610) 3225,565 3260,530 3750,530 3767.33,547.33 v1(3767.33,575)
  Layer 6 - Bottom Layer w5: v1(3225,610) R133.2@3225,641.38
H_EMU3: J4.17 U13.F14 | length 1876.6
  Layer 1 - Top Layer w4: v3(3461.42,1631.2) 3461.42,1626.37 U13.F14@3474.41,1620.87
  Layer 1 - Top Layer w5: v1(3727.96,450.6) J4.17@3727.96,512.8
  Layer 3 - Signal / PWR w4: 3402.49,1504.06 3402.99,1504.56 3402.99,1530.87 3403.03,1530.91 3403.03,1549.36 3404.21,1550.54 3404.99,1551.39 3404.99,1552.04 3406,1553.05 3406,1609.92 3416.97,1623.26 3436,1627 3449.51,1624.55 v3(3461.42,1631.2)
  Layer 3 - Signal / PWR w5.25: 3402.49,1504.05 3402.49,1471.99 3380.5,1450 3380.5,1250.5 3190,1059.99 3190,545 3220,515 3635,515 3699.4,450.6 v1(3727.96,450.6)
H_EMU4: J4.23 U13.F13 | length 1364.6
  Layer 1 - Top Layer w4: U13.F13@3500,1620.87 v3(3512.49,1610.82)
  Layer 1 - Top Layer w5: v1(3640,660) 3660,640 3660,595 3668.9,586.1 J4.23@3668.9,512.8
  Layer 6 - Bottom Layer w4: 3495,1456.06 3492.94,1464 3481,1510 3480.9,1578.5 3512.49,1610.09 v3(3512.49,1610.82)
  Layer 6 - Bottom Layer w5: 3495,1456.06 3505,1446.06 3505,1005 3580,930 3725,930 3735,920 3735,851 3640,756 v1(3640,660)
H_EMU5: J4.25 U13.D8 | length 1403.5
  Layer 1 - Top Layer w4: v3(3614,1558.2) U13.D8@3627.95,1569.69
  Layer 1 - Top Layer w5: v1(3615,680) 3615,655 3640,630 3640,595 3649.22,585.78 J4.25@3649.22,512.8
  Layer 3 - Signal / PWR w4: v3(3614,1558.2) 3635,1537.2
  Layer 3 - Signal / PWR w5.25: v1(3615,680) 3625,690 3680,690 3715,725 3810,725 3875,790 3875,1335 3685,1525 3647.2,1525 3635,1537.2
H_EMU6: J4.27 U13.B7 | length 1250.9
  Layer 1 - Top Layer w4: U13.B7@3653.54,1518.5 3666.3,1505.74 3666.3,1464
  Layer 1 - Top Layer w5: J4.27@3629.53,512.8 3629.53,575.47 3620,585 3620,625 3590,655 3590,700 3640,750 v1(3715,750) ; 3666.3,1464 3666.3,1459.7 3760.5,1365.5 3760.5,1339.5 3845,1255 3845,980 v1(3800,935)
  Layer 3 - Signal / PWR w5.25: v1(3715,750) 3800,835 v1(3800,935)
H_EMU7: J4.29 U13.C7 | length 2187.5
  Layer 1 - Top Layer w4: U13.C7@3653.6,1544 3666.3,1531.3 3713.3,1531.3 3717.5,1535.5 3717.5,1546.88 3720.6,1552.8 3728.96,1571.06 v3(3741.1,1583.2)
  Layer 1 - Top Layer w5: v1(3609.85,450.6) J4.29@3609.85,512.8
  Layer 3 - Signal / PWR w4: v3(3741.1,1583.2) 3743.8,1583.2 3759.69,1567.31 3796.79,1567.31 3810.22,1553.88 3837,1553.88
  Layer 3 - Signal / PWR w5.25: v1(3609.85,450.6) 3700.44,360 4075,360 4143,428 4143,773 4170,800 4170,860 4185,875 4185,920 4170,935 4170,1229 3845.12,1553.88 3837,1553.88
H_EMU8: J4.31 U13.E8 | length 1515.8
  Layer 1 - Top Layer w4: v3(3612.7,1603.2) 3613.2,1603.7 3619.53,1603.7 U13.E8@3627.95,1595.28
  Layer 1 - Top Layer w5: v1(3590,625) 3590.16,624.84 J4.31@3590.16,512.8
  Layer 3 - Signal / PWR w4: v3(3612.7,1603.2) 3630.1,1603.2 3654.41,1578.89
  Layer 3 - Signal / PWR w5.25: v1(3590,625) 3600,635 3650,635 3720,705 3881.56,705 3910,733.44 3910,950 3930,970 3930,1303.3 3654.41,1578.89
H_EMU9: J4.33 U13.B8 | length 1378
  Layer 1 - Top Layer w4: U13.B8@3627.95,1518.5 3640.7,1505.75 3640.7,1464
  Layer 1 - Top Layer w5: J4.33@3570.48,512.8 v1(3570.48,575) ; 3640.7,1464 3640.7,1457 3730,1367.7 3730,1280 3775,1235 3775,1150 3710,1085 v1(3710,905)
  Layer 3 - Signal / PWR w5.25: v1(3570.48,575) 3570.48,545.48 3560,535 3511.42,535 3495,551.42 3495,750 3545,800 3640,800 3710,870 v1(3710,905)
H_EMU10: J4.35 U13.C8 | length 1347.2
  Layer 1 - Top Layer w4: v3(3614.6,1535.8) 3616.7,1535.9 U13.C8@3627.95,1544.09
  Layer 1 - Top Layer w5: J4.35@3550.79,512.8 3550.79,710.79 v1(3575,735)
  Layer 3 - Signal / PWR w4: 3614.6,1519.39 v3(3614.6,1535.8)
  Layer 3 - Signal / PWR w5.25: v1(3575,735) 3665,735 3775,845 3775,1015 3855,1095 3855,1255 3820,1290 3820,1365 3679,1506 3627.99,1506 3614.6,1519.39
H_EMU11: J4.37 U13.B9 | length 1283
  Layer 1 - Top Layer w4: U13.B9@3602.36,1518.5 3615.1,1505.76 3615.1,1455.1
  Layer 1 - Top Layer w5: J4.37@3531.11,512.8 v1(3531.11,575) ; 3615.1,1455.1 3615.1,1425 3630,1410.1 3630,920 v1(3645,905)
  Layer 3 - Signal / PWR w5.25: v1(3531.11,575) 3531.11,756.11 3555,780 3650,780 3735,865 3735,920 3725,930 3700,930 3675,905 v1(3645,905)
H_EMU12: J4.39 U13.A7 | length 1336.1
  Layer 1 - Top Layer w4: 3653.54,1464 U13.A7@3653.54,1492.91
  Layer 1 - Top Layer w5: v1(3420,750) 3420,715 3511.42,623.58 J4.39@3511.42,512.8 ; 3653.54,1464 3653.54,1458.31 3745,1366.85 3745,1290 3790,1245 3790,1130 3740,1080 3740,905 3710,875 v1(3680,875)
  Layer 3 - Signal / PWR w5.25: v1(3420,750) 3420,770 3440,790 3510,790 3540,820 3625,820 v1(3680,875)
H_EMU13: J4.41 U13.A9 | length 1243.9
  Layer 1 - Top Layer w4: 3602.36,1457.36 U13.A9@3602.36,1492.91 3602.36,1484.64
  Layer 1 - Top Layer w5: v1(3370,790) 3370,690 3385,675 3435,675 3491.74,618.26 J4.41@3491.74,512.8 ; 3602.36,1457.36 3602.36,1412.64 3610,1405 v1(3610,905)
  Layer 3 - Signal / PWR w5.25: v1(3370,790) 3410,830 3494,830 3524,860 3565,860 v1(3610,905)
H_EMU14: J4.43 U13.A8 | length 1274.4
  Layer 1 - Top Layer w4: 3627.95,1464 U13.A8@3627.95,1492.91
  Layer 1 - Top Layer w5: J4.43@3472.05,512.8 v1(3472.05,575) ; v1(3615,875) 3650,875 3685,910 3685,1275 3715,1305 3715,1368.55 3627.95,1455.6 3627.95,1464
  Layer 3 - Signal / PWR w5.25: v1(3472.05,575) 3472.05,602.95 3395,680 3395,780 3425,810 3500,810 3530,840 3580,840 v1(3615,875)
H_EMU15: J4.45 U13.A11 | length 1203.7
  Layer 1 - Top Layer w4: 3551.18,1461.18 U13.A11@3551.18,1492.91
  Layer 1 - Top Layer w5: v1(3345,805) 3345,670 3360,655 3430,655 3452.37,632.63 J4.45@3452.37,512.8 ; v1(3490,860) 3490,1075 3510,1095 3510,1390 3551.18,1431.18 3551.18,1461.18
  Layer 3 - Signal / PWR w5.25: v1(3345,805) 3385,845 3475,845 v1(3490,860)
H_EMU16: J4.47 U13.F10 | length 1766.5
  Layer 1 - Top Layer w4: U13.F10@3576.77,1620.87 v3(3589.7,1611.1)
  Layer 1 - Top Layer w5: J4.47@3432.68,512.8 v1(3432.68,575)
  Layer 3 - Signal / PWR w4: 3565,1500 3565,1586.4 v3(3589.7,1611.1)
  Layer 3 - Signal / PWR w5.25: v1(3432.68,575) 3432.68,547.68 3420,535 3280,535 3255,560 3255,855 3360,960 3585,960 3685,1060 3685,1275 3720,1310 3720,1375 3645,1450 3615,1450 3565,1500
H_EMU17: J4.49 U13.A10 | length 1300.9
  Layer 1 - Top Layer w4: 3576.77,1461.77 U13.A10@3576.77,1492.91 U13.A10@3580,1489.68
  Layer 1 - Top Layer w5: J4.49@3413,512.8 v1(3413,600) ; v1(3545,915) 3545,1095 3540,1100 3540,1380 3576.77,1416.77 3576.77,1461.77
  Layer 3 - Signal / PWR w5.25: v1(3413,600) 3413,617 3395,635 3315,635 3295,655 3295,835 3365,905 3535,905 v1(3545,915)
H_EMU18: J4.51 U13.B10 | length 1276.1
  Layer 1 - Top Layer w4: U13.B10@3576.77,1518.5 3589.6,1505.67 3589.6,1460.4
  Layer 1 - Top Layer w5: v1(3320,825) 3320,660 3345,635 3380,635 3393.31,621.69 J4.51@3393.31,512.8 ; v1(3575,905) 3589.6,919.6 3589.6,1460.4
  Layer 3 - Signal / PWR w5.25: v1(3320,825) 3380,885 3555,885 v1(3575,905)
H_EMU19: J4.53 U13.E10 | length 1709.2
  Layer 1 - Top Layer w4: U13.E10@3576.77,1595.28 v3(3589.4,1585.1)
  Layer 1 - Top Layer w5: J4.53@3373.63,512.8 v1(3373.63,600)
  Layer 3 - Signal / PWR w4: 3574,1525 3574,1569.7 v3(3589.4,1585.1)
  Layer 3 - Signal / PWR w5.25: v1(3373.63,600) 3373.63,560 3363.63,550 3290,550 3275,565 3275,845 3370,940 3595,940 3765,1110 3765,1260 3735,1290 3735,1378.12 3642.28,1470.84 3614.16,1470.84 3574,1511 3574,1525
H_JTAG_RTCK: J4.7 R134.2 | length 2443.9
  Layer 1 - Top Layer w5: R134.2@2795,1406.38 2795,1365 2850,1310 2850,1230 2885,1195 2990,1195 v2(3020,1165) ; v1(3826.38,450.6) J4.7@3826.38,512.8
  Layer 6 - Bottom Layer w5: v2(3020,1165) 3020,975 3165,830 3165,565 3060,460 3060,280 3140,200 3695,200 3750,255 3750,415 3785.6,450.6 v1(3826.38,450.6)
H_JTAG_TCK: J4.3 R55.1 U13.K21 | length 4089.5
  Layer 1 - Top Layer w4: v3(3284.6,1710.1) U13.K21@3295.28,1723.23
  Layer 1 - Top Layer w5: J4.3@3865.75,512.8 3865.75,595.75 v1(3875,605)
  Layer 4 - Signal / PWR w4: 3163,1567.01 3200,1604.01 3200,1625 3220.94,1645.94 3305.94,1645.94 3326.18,1666.18 3326.18,1699.62 3322.11,1703.69 3322.11,1715 3312.11,1725 3300,1725 3285.1,1710.1 v3(3284.6,1710.1)
  Layer 4 - Signal / PWR w5.25: 3079.12,1500.13 3044.21,1500.13 2980.96,1436.88 2922.38,1436.88 2850,1364.49 2850,1225 2800,1175 2800,915 2770,885 2770,817.43 2707.57,755 2640,755 2625,740 2625,560 2685,500 2685,125 2745,65 3915,65 3945,95 3945,535 v1(3875,605) ; 3079.13,1500.12 3096.11,1500.12 3163,1567.01
  Layer 6 - Bottom Layer w5: v1(3875,605) R55.1@3875,636.38
H_JTAG_TDI: J4.5 U13.L23 | length 3442.3
  Layer 1 - Top Layer w4: v3(3234,1762.1) U13.L23@3244.09,1748.82
  Layer 1 - Top Layer w5: J4.5@3846.07,512.8 v1(3846.07,575)
  Layer 3 - Signal / PWR w5.25: v1(2675,1270) 2675,1215 2695,1195 2945,1195 3005,1135 v1(3045,1135)
  Layer 4 - Signal / PWR w4: 3163,1758 3167.1,1762.1 v3(3234,1762.1)
  Layer 4 - Signal / PWR w5.25: v1(2675,1270) 2675,1415 2833.39,1573.39 2923.87,1573.39 3002.86,1652.38 3057.38,1652.38 3163,1758
  Layer 6 - Bottom Layer w5: v1(3045,1135) 3045,980 3185,840 3185,555 3080,450 3080,285 3145,220 3285,220 3320,255 3355,255 3390,220 3690,220 3730,260 3730,420 3780,470 3815,470 3846.07,501.07 v1(3846.07,575)
H_JTAG_TDO: J4.4 R135.2 | length 2257.8
  Layer 1 - Top Layer w5: J4.4@3865.75,287.21 3865.75,224.25 v1(3887.5,202.5)
  Layer 6 - Bottom Layer w5: R135.2@2920,1361.38 2920,1358 2941,1337 2941,1184 2975,1150 2975,960 3125,810 3125,583.28 3020,478.28 3020,261.72 3121.72,160 3860,160 3887.5,187.5 v1(3887.5,202.5)
H_JTAG_TMS: J4.2 R51.1 U13.L21 | length 3361.5
  Layer 1 - Top Layer w4: v3(3279.4,1766.4) U13.L21@3295.28,1748.82
  Layer 1 - Top Layer w5: J4.2@3885.44,287.21 3885.44,229.56 3895,220 v1(3910,220) R51.1@3941.38,220
  Layer 4 - Signal / PWR w4: 3163,1712.99 3189.13,1739.12 3252.72,1739.12 3279.4,1765.8 v3(3279.4,1766.4)
  Layer 4 - Signal / PWR w5.25: v1(2842.37,1486.88) 2907.49,1552 2931.48,1552 3011.36,1631.88 3107.37,1631.88 3118.99,1643.5 3118.99,1668.98 3163,1712.99
  Layer 6 - Bottom Layer w5: v1(2842.37,1486.88) 2842.37,1422.37 2760,1340 2760,1230 2790,1200 2860,1200 2880,1180 2880,891.72 2916.72,855 3020,855 3085,790 3085,599.85 2980,494.85 2980,245.15 3105.15,120 3900,120 3935,155 3935,195 v1(3910,220)
H_JTAG_TRSTN: R56.1 R57.1 U13.L22 | length 3454.9
  Layer 1 - Top Layer w4: v3(3257,1764.6) U13.L22@3269.68,1748.82
  Layer 1 - Top Layer w5: v1(2826.5,1515) 2855,1515 2870,1500 2870,1248.78 2903.78,1215 v2(2965,1215)
  Layer 1 - Top Layer w5.25: R56.1@3777.01,605 v1(3777.01,625) ; v1(3780,200) R57.1@3802.01,200
  Layer 4 - Signal / PWR w4: 3163,1743 3167.11,1747.11 3240.21,1747.11 3257,1763.9 v3(3257,1764.6)
  Layer 4 - Signal / PWR w5.25: v1(2826.5,1515) 2855,1515 2902.25,1562.25 2927.23,1562.25 3007.11,1642.13 3062.13,1642.13 3163,1743
  Layer 6 - Bottom Layer w5: v2(2965,1215) 2995,1185 2995,970 3145,820 3145,575 3040,470 3040,270 3130,180 3760,180 v1(3780,200) 3768,212 3768,403 3790,425 3865,425 3880,440 3880,570 3850,600 3787.01,600 3777.01,610 v1(3777.01,625)
H_PMIC_INT: R91.1 TP57.1 U13.AB10 U25.9 U26.9 | length 9309.6
  Layer 1 - Top Layer w4: U13.AB10@3576.77,2030.32 v3(3607.6,2050)
  Layer 1 - Top Layer w5: U26.9@2839.37,791.54 2839.37,824.37 v1(2860,845) ; U25.9@4541.54,2410.63 4574.37,2410.63 v1(4595,2390)
  Layer 4 - Signal / PWR w4: v3(3607.6,2050) 3607.6,2136
  Layer 4 - Signal / PWR w5.25: 3607.6,2136 3610,2138.39 v2(3610,2300)
  Layer 6 - Bottom Layer w5: v1(2860,845) 2826.85,878.15 2523.15,878.15 2465,820 2465,340 2430,305 2000,305 1625,680 1355,680 1270,595 1015,595 985,625 985,1225 890,1320 890,1600 965,1675 1485,1675 1535,1725 1535,2455 1780,2700 2090,2700 2130,2740 2755,2740 2800,2785 3330,2785 3540,2575 3540,2330 3585,2285 3595,2285 v2(3610,2300) 3610,2315 3590,2335 3590,2455 3610,2475 3675,2475 3700,2500 3770.63,2500 3810.31,2460.32 R91.1@3915,2460.32 3915.31,2460 TP57.1@3980,2460 4085,2355 4310,2355 4330,2375 4365,2375 4385,2355 4515,2355 4550,2390 v1(4595,2390)
H_PORZ: R41.1 TP58.1 U5.23 U9.3 U13.F19 U25.10 U25.27 U26.27 | length 14910.8
  Layer 1 - Top Layer w4: U13.F19@3346.46,1620.87 v3(3359.3,1630.7)
  Layer 1 - Top Layer w5: U26.27@2839.37,608.46 2839.37,575.63 v1(2860,555) ; v1(4305,2390) 4325.63,2410.63 U25.27@4358.46,2410.63 ; U25.10@4541.54,2430.31 4584.69,2430.31 v1(4595,2420) ; v1(5455.63,1340.63) U9.3@5455.63,1367.83
  Layer 3 - Signal / PWR w5.25: v1(4684.69,2925) 4925,2925 5145.83,2704.17 5145.83,2454.17 5275,2325 5275,2230 5290,2215 5315,2215 v1(5335,2235)
  Layer 4 - Signal / PWR w5.25: v1(2860,555) 2860,610 2891.54,641.54 2891.54,723.46 2860,755 2860,800 2900,840 2900,1190 2930,1220 2930,1330 2975,1375 3030,1375 v1(3070,1415)
  Layer 6 - Bottom Layer w4: 3288.01,1464 3335.82,1511.81 3335.82,1545.82 3344.54,1554.54 3344.54,1611.74 3359.3,1626.5 v3(3359.3,1630.7)
  Layer 6 - Bottom Layer w5: v1(2860,555) 2645,555 2565,475 2565,280 2405,120 1013.43,120 755,378.43 755,3176.57 893.43,3315 4620,3315 4684.69,3250.31 v1(4684.69,2925) R41.1@4684.69,2810 4685,2809.69 TP58.1@4685,2750 4620,2685 4620,2445 v1(4595,2420) 4335,2420 v1(4305,2390) ; v1(3070,1415) 3239.02,1415 3288.01,1464 ; U5.23@5309.21,2385.83 5309.21,2365.79 5335,2340 v1(5335,2235) 5335,1990 5355,1970 5620,1970 5660,1930 5660,1625 5630,1595 5415,1595 5400,1580 5400,1396.26 v1(5455.63,1340.63)
I2C_SCL: R131.1 TP56.1 U13.G22 U25.17 U26.17 | length 11098
  Layer 1 - Top Layer w4: v3(3261.9,1630.4) 3261.28,1633.11 U13.G22@3269.68,1646.46
  Layer 1 - Top Layer w5: v2(2655,730) 2665.32,719.68 U26.17@2708.46,719.68 ; U25.17@4469.69,2541.54 4469.69,2584.69 v2(4480,2595)
  Layer 4 - Signal / PWR w4: 3163,1552.51 3210,1599.51 3210,1615 3225.4,1630.4 v3(3261.9,1630.4)
  Layer 4 - Signal / PWR w5.25: v2(2655,730) 2665.32,719.68 2693.47,719.68 2785,811.21 2785,875 2865,955 2865,1364.99 2926.63,1426.63 2985.21,1426.63 3048.46,1489.88 3074.87,1489.88 ; 3074.88,1489.87 3100.36,1489.87 3163,1552.51
  Layer 6 - Bottom Layer w5: v2(2655,730) 2680,705 2680,680 2545,545 2545,290 2395,140 1021.72,140 775,386.72 775,3168.28 901.72,3295 4435,3295 4497.99,3232.01 R131.1@4497.99,2810 4497.99,2757.99 TP56.1@4490,2750 4515,2725 4515,2630 v2(4480,2595)
I2C_SDA: R132.1 TP55.1 U13.G23 U25.18 U26.18 | length 10840.2
  Layer 1 - Top Layer w4: v3(3239.1,1599.7) 3231.2,1607.6 3231.2,1633.6 U13.G23@3244,1646.4
  Layer 1 - Top Layer w5: v2(2655,690) 2665,700 U26.18@2708.46,700 ; v2(4440,2595) 4450,2585 U25.18@4450,2541.54
  Layer 4 - Signal / PWR w4: 3163,1490.48 3215,1542.48 3215,1575 3239.1,1599.1 v3(3239.1,1599.7)
  Layer 4 - Signal / PWR w5.25: v2(2655,690) 2665,700 2695,700 2800,805 2800,865 2880,945 2880,1359.99 2910.39,1390.39 3000.26,1390.39 3052.81,1442.94 3115.46,1442.94 3163,1490.48
  Layer 6 - Bottom Layer w5: v2(2655,690) 2525,560 2525,300 2385,160 1030,160 795,395 795,3160 910,3275 4345,3275 4407.01,3212.99 R132.1@4407.01,2810 4407.01,2752.99 TP55.1@4410,2750 4440,2720 v2(4440,2595)
MDC: U5.25 U9.1 U13.D10 | length 4316.9
  Layer 1 - Top Layer w4: U13.D10@3576.77,1569.69 v3(3590,1559.1)
  Layer 1 - Top Layer w5: v1(5235,1345) 5410,1345 5416.26,1351.26 U9.1@5416.26,1367.83
  Layer 6 - Bottom Layer w4: 3572.8,1513.83 3572.8,1545.1 v3(3590,1559.1)
  Layer 6 - Bottom Layer w5: 3572.8,1513.83 3572.8,1512.2 3620,1465 3620,1125 3655,1090 3810,1090 3925,975 3925,880 3975,830 4410,830 4560,680 5170,680 5235,745 v1(5235,1345) 5215,1365 5185,1365 5160,1390 5160,1720 5295,1855 5295,2188.56 5269.84,2213.72 U5.25@5269.84,2385.83
MDIO: R2.1 R18.1 U5.24 U9.36 U13.C10 | length 5651.9
  Layer 1 - Top Layer w4: U13.C10@3576.77,1544.09 v3(3589.1,1534)
  Layer 1 - Top Layer w5.25: v2(5380.83,1380) U9.36@5380.83,1403.26
  Layer 3 - Signal / PWR w4: 3589.1,1519.9 v3(3589.1,1534)
  Layer 3 - Signal / PWR w5.25: 3589.1,1519.9 3619,1490 3670,1490 3765,1395 3765,1295 3790,1270 3790,1060 3755,1025 3755,855 3660,760 3565,760 3550,745 3550,630 3585,595 3630,595 3720,685 3890,685 4045,530 v1(4070,530)
  Layer 6 - Bottom Layer w5: U5.24@5289.53,2385.83 5289.53,2360.47 5310,2340 R18.1@5310,2310.99 5290.99,2310.99 5285,2305 5285,2220 5315,2190 5315,2095
  Layer 6 - Bottom Layer w5.25: v1(4070,530) 5095,530 5155,470 5275,470 5380,575 5380,1245 5425,1290 5425,1340 5412.01,1352.99 R2.1@5390,1352.99 5390,1370.83 v2(5380.83,1380) 5380.83,1590.83 5405,1615 5620,1615 5640,1635 5640,1920 5610,1950 5345,1950 5315,1980 5315,2095
MII0_COL: R20.1 U13.L5 | length 2227.1
  Layer 1 - Top Layer w4: U13.L5@3704.8,1748.8 v3(3714.8,1761.7)
  Layer 3 - Signal / PWR w4: v3(3714.8,1761.7) 3737.98,1738.52 3777.48,1738.52 3803,1713 3837,1713
  Layer 3 - Signal / PWR w5.25: 3837,1713 3872,1678 4333,1678 4360,1705 4980,1705 5045,1770 5045,2465 5020,2490 v6(4980,2490)
  Layer 6 - Bottom Layer w5.25: v6(4980,2490) R20.1@5017.44,2490
MII0_CRS: R136.1 U13.P4 | length 1743
  Layer 1 - Top Layer w4: U13.P4@3730.4,1825.6 v3(3737.9,1841.6)
  Layer 3 - Signal / PWR w4: v3(3737.9,1841.6) 3752.89,1826.61 3821.61,1826.61 3835.01,1840
  Layer 3 - Signal / PWR w5.25: 3835.01,1840 4270,1840 4320,1890 4725,1890 4830,1995 4830,2340 4850,2360 4895,2360 4935,2400 v6(4980,2400)
  Layer 6 - Bottom Layer w5.25: v6(4980,2400) R136.1@5017.44,2400
MII0_RX_CLK: R137.1 U13.N6 | length 1774.2
  Layer 1 - Top Layer w4: U13.N6@3679.13,1800 v3(3689,1786.6)
  Layer 3 - Signal / PWR w5.25: v1(4325,1820) 4760,1820 4875,1935 4875,2245.81 4939.19,2310 v6(4980,2310)
  Layer 4 - Signal / PWR w4: v3(3689,1786.6) 3689,1786.7 3708.88,1806.58 3786.52,1806.58 3795.5,1797.6 3837,1797.6
  Layer 4 - Signal / PWR w5.25: 3837,1797.6 3872.6,1797.6 3922.5,1847.5 4297.5,1847.5 v1(4325,1820)
  Layer 6 - Bottom Layer w5.25: v6(4980,2310) R137.1@5017.44,2310
MII0_RX_D0: R138.1 U13.R1 | length 1870.8
  Layer 1 - Top Layer w4: U13.R1@3807.09,1851.18 3837,1881.09
  Layer 1 - Top Layer w5: 3837,1881.09 3891.44,1935.52 3975.52,1935.52 4010,1970 4965,1970 5005,2010 5005,2517.44 4987.44,2535 v6(4950,2535)
  Layer 6 - Bottom Layer w5.25: v6(4950,2535) R138.1@4987.44,2535
MII0_RX_D1: R139.1 U13.R2 | length 1985.9
  Layer 1 - Top Layer w4: U13.R2@3781.5,1851.18 3794.19,1838.49 3819.49,1838.49 3837,1856
  Layer 1 - Top Layer w5: 3837,1856 3871.01,1890 3955,1890 4015,1950 4310,1950 4330,1930 4955,1930 5025,2000 5025,2565 5010,2580 v6(4980,2580)
  Layer 6 - Bottom Layer w5.25: v6(4980,2580) R139.1@5017.44,2580
MII0_RX_D2: R140.1 U13.T5 | length 1886.9
  Layer 1 - Top Layer w4: v3(3695.32,1863.94) U13.T5@3704.72,1876.77
  Layer 3 - Signal / PWR w4: v3(3695.32,1863.94) 3721.38,1890 3837,1890
  Layer 3 - Signal / PWR w5.25: 3837,1890 3955,1890 4015.01,1950 4655,1950 4705,2000 4705,2330 4795,2420 4865,2420 4900,2455 4900,2575 v6(4950,2625)
  Layer 6 - Bottom Layer w5.25: v6(4950,2625) R140.1@4987.44,2625
MII0_RX_D3: R141.1 U13.T4 | length 1937.7
  Layer 1 - Top Layer w4: U13.T4@3730.31,1876.77 v3(3740.6,1864.1)
  Layer 3 - Signal / PWR w4: v3(3740.6,1864.1) 3755.39,1878.89 3837,1878.89
  Layer 3 - Signal / PWR w5.25: 3837,1878.89 3983.89,1878.89 4005,1900 4145,1900 4170,1875 4245,1875 4300,1930 4660,1930 4720,1990 4720,2320 4800,2400 4875,2400 4925,2450 4925,2565 4980,2620 v6(4980,2670)
  Layer 6 - Bottom Layer w5.25: v6(4980,2670) R141.1@5017.44,2670
MII0_RX_DV: R143.1 U13.N5 | length 1959
  Layer 1 - Top Layer w4: U13.N5@3704.72,1800 v3(3714.5,1786.8)
  Layer 3 - Signal / PWR w5.25: v1(4305,1775) 4920,1775 5015,1870 5015,2335 4995,2355 v6(4950,2355)
  Layer 4 - Signal / PWR w4: v3(3714.5,1786.8) 3726.29,1798.59 3777.61,1798.59 3791.1,1785.1 3837,1785.1
  Layer 4 - Signal / PWR w5.25: 3837,1785.1 3880.1,1785.1 3895.01,1800 3925,1800 3930,1795 4285,1795 v1(4305,1775)
  Layer 6 - Bottom Layer w5.25: v6(4950,2355) R143.1@4987.44,2355
MII0_RX_ER: R142.1 U13.P3 | length 1705.1
  Layer 1 - Top Layer w4: U13.P3@3756,1825.6 v3(3764,1841.6)
  Layer 3 - Signal / PWR w4: v3(3764,1841.6) 3816.6,1841.6 3823.75,1848.74
  Layer 3 - Signal / PWR w5.25: 3823.75,1848.74 3830.01,1855 4253,1855 4308,1910 4720,1910 4805,1995 4805,2360 4825,2380 4885,2380 v6(4950,2445)
  Layer 6 - Bottom Layer w5.25: v6(4950,2445) R142.1@4987.44,2445
MII0_TX_CLK: R17.1 U13.N2 | length 2915.7
  Layer 1 - Top Layer w4: U13.N2@3781.5,1800 3794.4,1787.1 3817.9,1787.1 3823.1,1781.9 3837,1781.9
  Layer 1 - Top Layer w5: 3837,1781.9 3848.1,1781.9 3930,1700 4340,1700 4420,1780 5060,1780 5145,1865 5145,2535 5230,2620 5375,2620 5425,2670 5425,2820 5405,2840 5275,2840 5255,2820 v6(5255,2760)
  Layer 6 - Bottom Layer w5: R17.1@5215,2760 v6(5255,2760)
MII0_TX_D0: U5.4 U13.N4 | length 2589.1
  Layer 1 - Top Layer w4: U13.N4@3730.31,1800 v3(3739.6,1783.6)
  Layer 1 - Top Layer w5: v2(4965,1855) 5065,1955 5065,2570 5195,2700 5282,2700 5305,2723 v6(5305,2760)
  Layer 3 - Signal / PWR w4: v3(3739.6,1783.6) 3754.59,1798.59 3775.41,1798.59 3815,1759 3837,1759
  Layer 3 - Signal / PWR w5.25: 3837,1759 3895.99,1759 3906.86,1748.13 4018.13,1748.13 4045,1775 4165,1775 4185,1795 4905,1795 v2(4965,1855)
  Layer 6 - Bottom Layer w5: U5.4@5230.47,2614.17 5230.47,2648.47 5305,2723 v6(5305,2760)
